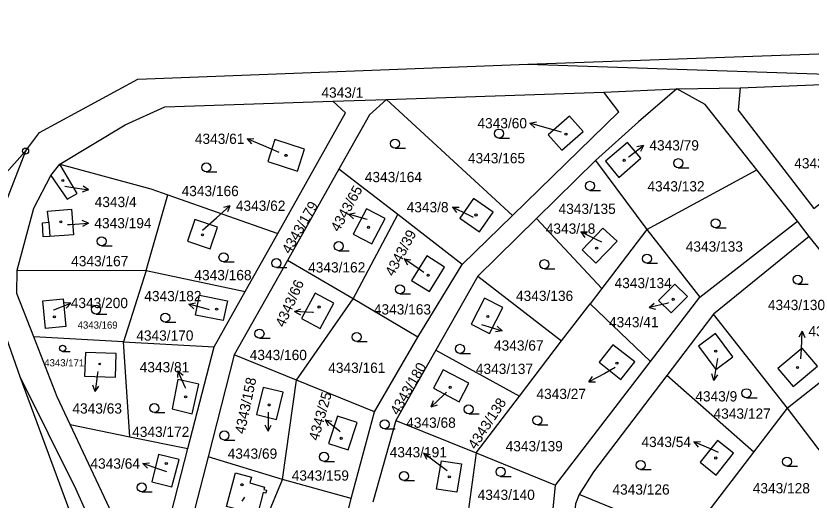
# Model space of a CAD drawing. Extents: x -733394 to -722299, y -1082822 to -1075049.
# Drawn here: x -729669.4 to -729537.5, y -1077903.2 to -1077822.8 of the extents above; entities that cross this region are included whole.
import ezdxf

# ---------------------------------------------------------------- set-up
doc = ezdxf.new("R2010")
doc.units = 0
for name, color, linetype in [('Hranice parcel', 7, 'Continuous'), ('Parcelní čísla', 7, 'Continuous'), ('Pop  PČ popisy', 7, 'Continuous'), ('Vnitřní kresba', 7, 'Continuous'), ('Značky bodu BP', 7, 'Continuous'), ('Značky budov', 7, 'Continuous'), ('Značky kultur', 7, 'Continuous')]:
    doc.layers.add(name, color=color, linetype=linetype)

msp = doc.modelspace()

# ---------------------------------------------------------------- linework, layer by layer
at = {"layer": 'Hranice parcel'}
for p, q in [((-729549.31, -1077834.75), (-729513.26, -1077833.28)), ((-729607.94, -1077836.69), (-729571.93, -1077835.5)), ((-729571.93, -1077835.5), (-729559.79, -1077834.92)), ((-729559.79, -1077834.92), (-729549.31, -1077834.75)), ((-729616.86, -1077836.99), (-729607.94, -1077836.69)), ((-729587.08, -1077855.95), (-729607.94, -1077836.69)), ((-729677.33, -1077855.84), (-729667.81, -1077845.25)), ((-729667.81, -1077845.25), (-729675.27, -1077864.38)), ((-729573.27, -1077846.82), (-729583.07, -1077856.44)), ((-729573.27, -1077846.82), (-729564.79, -1077858.28)), ((-729663.65, -1077849.32), (-729662.16, -1077847.4)), ((-729615.86, -1077848.27), (-729624.38, -1077863.39)), ((-729606.1, -1077855.8), (-729615.86, -1077848.27)), ((-729564.79, -1077858.28), (-729546.55, -1077848.34)), ((-729539.8, -1077856.9), (-729546.55, -1077848.34)), ((-729647.8, -1077865.06), (-729644.24, -1077852.49)), ((-729644.24, -1077852.49), (-729626, -1077858.95)), ((-729613.48, -1077869.77), (-729606.1, -1077855.8)), ((-729595.38, -1077864.05), (-729606.1, -1077855.8)), ((-729595.38, -1077864.05), (-729587.08, -1077855.95)), ((-729583.07, -1077856.44), (-729592.83, -1077866.02)), ((-729583.07, -1077856.44), (-729572.23, -1077868.03)), ((-729555.96, -1077869.5), (-729539.8, -1077856.9)), ((-729537.82, -1077859.41), (-729539.8, -1077856.9)), ((-729631.39, -1077868.53), (-729626, -1077858.95)), ((-729564.79, -1077858.28), (-729572.23, -1077868.03)), ((-729564.79, -1077858.28), (-729555.96, -1077869.5)), ((-729537.82, -1077859.41), (-729553.73, -1077872.32)), ((-729525.41, -1077875.14), (-729537.82, -1077859.41)), ((-729675.27, -1077864.38), (-729668.75, -1077882.65)), ((-729624.38, -1077863.39), (-729633.23, -1077879.08)), ((-729613.48, -1077869.77), (-729624.38, -1077863.39)), ((-729602.78, -1077876.16), (-729595.38, -1077864.05)), ((-729669.21, -1077865.04), (-729647.8, -1077865.06)), ((-729647.8, -1077865.06), (-729651.59, -1077876.89)), ((-729647.8, -1077865.06), (-729631.39, -1077868.53)), ((-729592.83, -1077866.02), (-729599.78, -1077878.28)), ((-729592.83, -1077866.02), (-729578.9, -1077876.76)), ((-729572.23, -1077868.03), (-729574.19, -1077870.6)), ((-729636.56, -1077877.73), (-729631.39, -1077868.53)), ((-729622.86, -1077883.28), (-729613.48, -1077869.77)), ((-729602.78, -1077876.16), (-729613.48, -1077869.77)), ((-729564.14, -1077880.15), (-729555.96, -1077869.5)), ((-729578.9, -1077876.76), (-729574.19, -1077870.6)), ((-729574.19, -1077870.6), (-729564.14, -1077880.15)), ((-729553.73, -1077872.32), (-729561.44, -1077882.47)), ((-729541.43, -1077887.94), (-729553.73, -1077872.32)), ((-729651.59, -1077876.89), (-729666.45, -1077876.06)), ((-729609.95, -1077888.51), (-729602.78, -1077876.16)), ((-729525.41, -1077875.14), (-729541.43, -1077887.94)), ((-729650.53, -1077892.65), (-729651.59, -1077876.89)), ((-729651.59, -1077876.89), (-729636.56, -1077877.73)), ((-729585.89, -1077885.92), (-729578.9, -1077876.76)), ((-729640.9, -1077894.62), (-729636.56, -1077877.73)), ((-729599.78, -1077878.28), (-729606.38, -1077889.95)), ((-729599.78, -1077878.28), (-729585.89, -1077885.92)), ((-729633.23, -1077879.08), (-729637.55, -1077896.01)), ((-729622.86, -1077883.28), (-729633.23, -1077879.08)), ((-729579.9, -1077900.68), (-729564.14, -1077880.15)), ((-729547.02, -1077895.24), (-729561.44, -1077882.47)), ((-729625.23, -1077899.74), (-729622.86, -1077883.28)), ((-729609.95, -1077888.51), (-729622.86, -1077883.28)), ((-729593.08, -1077895.34), (-729585.89, -1077885.92)), ((-729547.02, -1077895.24), (-729541.43, -1077887.94)), ((-729529.41, -1077903.77), (-729541.43, -1077887.94)), ((-729613.82, -1077902.92), (-729609.95, -1077888.51)), ((-729648.42, -1077916.16), (-729660.41, -1077890.63)), ((-729660.41, -1077890.63), (-729650.53, -1077892.65)), ((-729606.38, -1077889.95), (-729610.2, -1077903.5)), ((-729606.38, -1077889.95), (-729593.08, -1077895.34)), ((-729650.53, -1077892.65), (-729640.9, -1077894.62)), ((-729637.55, -1077896.01), (-729641.89, -1077913.03)), ((-729625.23, -1077899.74), (-729637.55, -1077896.01)), ((-729593.08, -1077895.34), (-729594.79, -1077907.72)), ((-729593.08, -1077895.34), (-729579.9, -1077900.68)), ((-729557.98, -1077909.55), (-729547.02, -1077895.24)), ((-729631.27, -1077914.26), (-729625.23, -1077899.74)), ((-729613.82, -1077902.92), (-729625.23, -1077899.74)), ((-729581.26, -1077914.24), (-729579.9, -1077900.68)), ((-729557.98, -1077909.55), (-729575.99, -1077902.26)), ((-729617.11, -1077915.9), (-729613.82, -1077902.92))]:
    msp.add_line(p, q, dxfattribs=at)
for points in [[(-729584.53, -1077830.82), (-729511.39, -1077828.22), (-729503.43, -1077827.46), (-729475.38, -1077824.79), (-729463.28, -1077823.55), (-729456.4, -1077822.82)], [(-729584.53, -1077830.82), (-729528.32, -1077832.73), (-729478.29, -1077828.76), (-729456.16, -1077825.12)], [(-729667.81, -1077845.25), (-729665.54, -1077842.16), (-729649.22, -1077833.32), (-729584.53, -1077830.82)], [(-729549.31, -1077834.75), (-729549.62, -1077838.49), (-729537.08, -1077854.76), (-729513.33, -1077836.06), (-729513.26, -1077833.28)], [(-729587.08, -1077855.95), (-729569.44, -1077838.75), (-729571.93, -1077835.5)], [(-729559.79, -1077834.92), (-729566.15, -1077840.39), (-729573.27, -1077846.82)], [(-729546.55, -1077848.34), (-729555.08, -1077837.54), (-729559.79, -1077834.92)], [(-729607.94, -1077836.69), (-729610.77, -1077839.24), (-729615.86, -1077848.27)], [(-729662.16, -1077847.4), (-729651.29, -1077840.91), (-729644.75, -1077837.91), (-729616.86, -1077836.99)], [(-729626, -1077858.95), (-729614.73, -1077838.91), (-729616.86, -1077836.99)], [(-729578.87, -1077845.12), (-729575.34, -1077842), (-729577.6, -1077839.45), (-729581.12, -1077842.57), (-729578.87, -1077845.12)], [(-729621.55, -1077844.94), (-729626.45, -1077843.33), (-729627.64, -1077846.96), (-729622.73, -1077848.57), (-729621.55, -1077844.94)], [(-729567.95, -1077843.85), (-729571.65, -1077846.93), (-729569.4, -1077849.61), (-729565.76, -1077846.45), (-729567.95, -1077843.85)], [(-729663.65, -1077849.32), (-729660.93, -1077853.23), (-729659.24, -1077852.31), (-729662.16, -1077847.4)], [(-729662.16, -1077847.4), (-729647.02, -1077851.51), (-729644.24, -1077852.49)], [(-729669.21, -1077865.04), (-729666.43, -1077854.72), (-729663.65, -1077849.32)], [(-729592.55, -1077858.65), (-729590.26, -1077855.41), (-729593.51, -1077853.11), (-729595.8, -1077856.36), (-729592.55, -1077858.65)], [(-729665.04, -1077857.14), (-729663.95, -1077857.06), (-729664.17, -1077855.23), (-729660.19, -1077854.88), (-729659.9, -1077859.13), (-729663.78, -1077859.41), (-729664.88, -1077859.48), (-729665.04, -1077857.14)], [(-729610.37, -1077860.67), (-729608.18, -1077856.45), (-729611.29, -1077854.83), (-729613.48, -1077859.05), (-729610.37, -1077860.67)], [(-729636, -1077857.9), (-729639.75, -1077856.62), (-729640.97, -1077860.19), (-729637.22, -1077861.47), (-729636, -1077857.9)], [(-729575.5, -1077861.63), (-729573.21, -1077863.84), (-729569.71, -1077860.22), (-729572.09, -1077858.02), (-729575.5, -1077861.63)], [(-729601.27, -1077862.66), (-729603.79, -1077866.72), (-729600.84, -1077868.56), (-729598.31, -1077864.49), (-729601.27, -1077862.66)], [(-729666.45, -1077876.06), (-729669.26, -1077868.86), (-729669.21, -1077865.04)], [(-729558.04, -1077869.39), (-729560.1, -1077867.33), (-729562.82, -1077870.07), (-729560.76, -1077872.12), (-729558.04, -1077869.39)], [(-729661.59, -1077869.79), (-729661.15, -1077874.36), (-729664.52, -1077874.68), (-729664.97, -1077870.12), (-729661.59, -1077869.79)], [(-729638.98, -1077869.14), (-729634.33, -1077870.09), (-729635.04, -1077873.36), (-729639.65, -1077872.49), (-729638.98, -1077869.14)], [(-729616.7, -1077870.51), (-729619.81, -1077868.83), (-729622.07, -1077873.01), (-729618.95, -1077874.69), (-729616.7, -1077870.51)], [(-729588.66, -1077871.2), (-729591.69, -1077869.64), (-729593.91, -1077873.97), (-729590.88, -1077875.53), (-729588.66, -1077871.2)], [(-729660.41, -1077890.63), (-729662.57, -1077886.03), (-729666.45, -1077876.06)], [(-729550.51, -1077879.41), (-729553.38, -1077875.54), (-729556.18, -1077877.61), (-729553.32, -1077881.49), (-729550.51, -1077879.41)], [(-729566.75, -1077880.2), (-729570.39, -1077877.4), (-729572.69, -1077880.29), (-729569.07, -1077883.14), (-729566.75, -1077880.2)], [(-729652.93, -1077882.76), (-729652.79, -1077878.86), (-729657.9, -1077878.67), (-729658.04, -1077882.58), (-729652.93, -1077882.76)], [(-729540.5, -1077884.34), (-729536.47, -1077880.95), (-729538.99, -1077877.96), (-729543.02, -1077881.35), (-729540.5, -1077884.34)], [(-729600.16, -1077884.61), (-729595.88, -1077886.85), (-729594.27, -1077883.77), (-729598.54, -1077881.58), (-729600.16, -1077884.61)], [(-729668.75, -1077882.65), (-729659.48, -1077901.34), (-729652.78, -1077916.35), (-729643.8, -1077935.33), (-729632.76, -1077952.54), (-729622.2, -1077964.95), (-729556.97, -1078018.84)], [(-729668.75, -1077882.65), (-729648.84, -1077936.68), (-729633.06, -1077960.71), (-729557.22, -1078018.79)], [(-729561.44, -1077882.47), (-729573.6, -1077898.46), (-729575.99, -1077902.26)], [(-729642.57, -1077883.15), (-729643.53, -1077888.05), (-729640.21, -1077888.88), (-729639.1, -1077883.93), (-729642.57, -1077883.15)], [(-729628.43, -1077884.46), (-729629.53, -1077888.99), (-729626.2, -1077889.79), (-729625.11, -1077885.26), (-729628.43, -1077884.46)], [(-729614.3, -1077894.81), (-729612.84, -1077890.31), (-729616.09, -1077889.26), (-729617.55, -1077893.76), (-729614.3, -1077894.81)], [(-729553.04, -1077893.26), (-729555.93, -1077896.89), (-729553.27, -1077899.02), (-729550.37, -1077895.39), (-729553.04, -1077893.26)], [(-729648.42, -1077916.16), (-729646.44, -1077916.19), (-729640.9, -1077894.62)], [(-729642.35, -1077896.42), (-729645.76, -1077895.58), (-729646.89, -1077900.16), (-729643.58, -1077900.98), (-729642.35, -1077896.42)], [(-729598.85, -1077896.64), (-729595.51, -1077897.18), (-729596.28, -1077901.88), (-729599.64, -1077901.33), (-729598.85, -1077896.64)], [(-729629.37, -1077905.57), (-729634.48, -1077904.23), (-729633.02, -1077898.63), (-729630.32, -1077899.34), (-729630.6, -1077900.33), (-729628.19, -1077901), (-729628.3, -1077901.41), (-729627.86, -1077901.52), (-729627.98, -1077902.01), (-729628.42, -1077901.9), (-729629.37, -1077905.57)], [(-729575.99, -1077902.26), (-729576.6, -1077903.78), (-729577.71, -1077915.07)]]:
    msp.add_lwpolyline(points, dxfattribs=at)
at = {"layer": 'Pop  PČ popisy'}
for p, q in [((-729584.19, -1077840.61), (-729583.08, -1077840.41)), ((-729581.3, -1077841.44), (-729584.19, -1077840.61)), ((-729584.19, -1077840.61), (-729583.36, -1077841.37)), ((-729578.95, -1077842.09), (-729581.3, -1077841.44)), ((-729631.06, -1077843.22), (-729629.95, -1077843.15)), ((-729628.3, -1077844.39), (-729631.06, -1077843.22)), ((-729631.06, -1077843.22), (-729630.34, -1077844.07)), ((-729625.77, -1077845.48), (-729628.3, -1077844.39)), ((-729567.7, -1077846.16), (-729565.34, -1077844.31)), ((-729565.34, -1077844.31), (-729566.43, -1077844.53)), ((-729565.34, -1077844.31), (-729565.82, -1077845.32)), ((-729567.82, -1077846.26), (-729567.7, -1077846.16)), ((-729661.31, -1077851.08), (-729660.32, -1077851.24)), ((-729660.32, -1077851.24), (-729657.36, -1077851.71)), ((-729657.36, -1077851.71), (-729658.27, -1077851.06)), ((-729657.36, -1077851.71), (-729658.42, -1077852.05)), ((-729636.16, -1077856.33), (-729633.93, -1077854.32)), ((-729633.93, -1077854.32), (-729635.01, -1077854.62)), ((-729633.93, -1077854.32), (-729634.34, -1077855.36)), ((-729597.01, -1077854.58), (-729595.89, -1077854.57)), ((-729594.31, -1077855.9), (-729597.01, -1077854.58)), ((-729597.01, -1077854.58), (-729596.33, -1077855.47)), ((-729638.45, -1077858.4), (-729636.16, -1077856.33)), ((-729614.24, -1077855.72), (-729613.14, -1077855.52)), ((-729611.36, -1077856.55), (-729614.24, -1077855.72)), ((-729614.24, -1077855.72), (-729613.42, -1077856.48)), ((-729611.16, -1077856.61), (-729611.36, -1077856.55)), ((-729593.51, -1077856.29), (-729594.31, -1077855.9)), ((-729660.86, -1077857.44), (-729660.4, -1077857.41)), ((-729660.4, -1077857.41), (-729657.41, -1077857.2)), ((-729657.41, -1077857.2), (-729658.44, -1077856.77)), ((-729657.41, -1077857.2), (-729658.37, -1077857.77)), ((-729575.74, -1077858.68), (-729574.62, -1077858.67)), ((-729573.04, -1077860), (-729575.74, -1077858.68)), ((-729575.74, -1077858.68), (-729575.06, -1077859.57)), ((-729572.25, -1077860.39), (-729573.04, -1077860)), ((-729602.55, -1077864.85), (-729605.01, -1077863.13)), ((-729605.01, -1077863.13), (-729603.9, -1077863.29)), ((-729605.01, -1077863.13), (-729604.48, -1077864.11)), ((-729601.74, -1077865.41), (-729602.55, -1077864.85)), ((-729663.11, -1077871.62), (-729660.33, -1077870.5)), ((-729660.33, -1077870.5), (-729661.44, -1077870.41)), ((-729660.33, -1077870.5), (-729661.07, -1077871.33)), ((-729640.75, -1077870.66), (-729639.65, -1077870.44)), ((-729637.85, -1077871.44), (-729640.75, -1077870.66)), ((-729640.75, -1077870.66), (-729639.91, -1077871.41)), ((-729564.39, -1077871.21), (-729563.53, -1077870.49)), ((-729561.47, -1077870.53), (-729564.39, -1077871.21)), ((-729561.17, -1077870.46), (-729561.47, -1077870.53)), ((-729663.18, -1077871.65), (-729663.11, -1077871.62)), ((-729637.3, -1077871.58), (-729637.85, -1077871.44)), ((-729623.22, -1077871.87), (-729622.19, -1077871.43)), ((-729620.22, -1077872.03), (-729623.22, -1077871.87)), ((-729623.22, -1077871.87), (-729622.24, -1077872.43)), ((-729620.04, -1077872.04), (-729620.22, -1077872.03)), ((-729564.39, -1077871.21), (-729563.31, -1077871.47)), ((-729592.19, -1077874.03), (-729591.65, -1077874.19)), ((-729591.65, -1077874.19), (-729588.78, -1077875.07)), ((-729588.78, -1077875.07), (-729589.88, -1077875.25)), ((-729588.78, -1077875.07), (-729589.59, -1077874.3)), ((-729538.98, -1077875.14), (-729539.54, -1077876.12)), ((-729539.14, -1077878.14), (-729538.98, -1077875.14)), ((-729538.98, -1077875.14), (-729538.54, -1077876.17)), ((-729539.24, -1077879.75), (-729539.14, -1077878.14)), ((-729553.16, -1077880.34), (-729553.63, -1077883.3)), ((-729553.05, -1077879.66), (-729553.16, -1077880.34)), ((-729570, -1077881.19), (-729571.76, -1077882.14)), ((-729655.88, -1077882.19), (-729656.3, -1077885.16)), ((-729655.83, -1077881.85), (-729655.88, -1077882.19)), ((-729642.56, -1077881.71), (-729642.61, -1077882.83)), ((-729641.34, -1077884.45), (-729642.56, -1077881.71)), ((-729642.56, -1077881.71), (-729641.7, -1077882.42)), ((-729571.76, -1077882.14), (-729574.41, -1077883.55)), ((-729574.41, -1077883.55), (-729573.76, -1077882.64)), ((-729553.63, -1077883.3), (-729553.97, -1077882.24)), ((-729553.63, -1077883.3), (-729552.98, -1077882.39)), ((-729656.3, -1077885.16), (-729656.65, -1077884.1)), ((-729656.3, -1077885.16), (-729655.66, -1077884.24)), ((-729574.41, -1077883.55), (-729573.29, -1077883.52)), ((-729641.25, -1077884.66), (-729641.34, -1077884.45)), ((-729598.37, -1077885.63), (-729600.57, -1077887.68)), ((-729597.99, -1077885.28), (-729598.37, -1077885.63)), ((-729600.57, -1077887.68), (-729600.17, -1077886.63)), ((-729600.57, -1077887.68), (-729599.49, -1077887.36)), ((-729627.58, -1077888.57), (-729627.58, -1077888.75)), ((-729627.58, -1077888.75), (-729627.58, -1077891.75)), ((-729627.58, -1077891.75), (-729628.08, -1077890.75)), ((-729627.58, -1077891.75), (-729627.08, -1077890.75)), ((-729615.77, -1077891.74), (-729618.1, -1077889.85)), ((-729618.1, -1077889.85), (-729617.01, -1077890.09)), ((-729618.1, -1077889.85), (-729617.64, -1077890.87)), ((-729615.65, -1077891.84), (-729615.77, -1077891.74)), ((-729556.97, -1077893.51), (-729555.85, -1077893.44)), ((-729554.21, -1077894.68), (-729556.97, -1077893.51)), ((-729556.97, -1077893.51), (-729556.25, -1077894.36)), ((-729552.86, -1077895.25), (-729554.21, -1077894.68)), ((-729599.41, -1077897.2), (-729601.81, -1077895.39)), ((-729601.81, -1077895.39), (-729600.71, -1077895.6)), ((-729601.81, -1077895.39), (-729601.31, -1077896.4)), ((-729648.38, -1077897.1), (-729647.27, -1077896.96)), ((-729645.54, -1077898.08), (-729648.38, -1077897.1)), ((-729648.38, -1077897.1), (-729647.59, -1077897.9)), ((-729597.87, -1077898.34), (-729599.41, -1077897.2)), ((-729644.38, -1077898.47), (-729645.54, -1077898.08)), ((-729631.52, -1077902.7), (-729631.97, -1077903.33))]:
    msp.add_line(p, q, dxfattribs=at)
at = {"layer": 'Vnitřní kresba'}
msp.add_line((-729663.95, -1077857.06), (-729663.78, -1077859.41), dxfattribs=at)
at = {"layer": 'Značky bodu BP'}
for radius in [0.5, 0.0303]:
    msp.add_circle((-729667.81, -1077845.25), radius, dxfattribs=at)
at = {"layer": 'Značky budov'}
for centre, radius in [((-729578.19, -1077842.46), 0.175), ((-729624.62, -1077845.97), 0.175), ((-729568.52, -1077846.78), 0.175), ((-729661.64, -1077850.13), 0.175), ((-729593.1, -1077855.86), 0.175), ((-729661.96, -1077857), 0.175), ((-729610.94, -1077857.91), 0.175), ((-729638.47, -1077859.16), 0.175), ((-729573.1, -1077861.35), 0.175), ((-729601.03, -1077865.86), 0.175), ((-729560.41, -1077869.85), 0.175), ((-729619.14, -1077871.13), 0.175), ((-729636.13, -1077871.49), 0.175), ((-729663.04, -1077872.75), 0.175), ((-729591.14, -1077872.69), 0.175), ((-729553.34, -1077878.46), 0.175), ((-729569.73, -1077880.46), 0.175), ((-729655.51, -1077880.58), 0.122), ((-729539.78, -1077881.17), 0.175), ((-729597.38, -1077884.46), 0.175), ((-729641.27, -1077886.03), 0.175), ((-729627.41, -1077887.38), 0.175), ((-729615.47, -1077892.93), 0.175), ((-729553.34, -1077896.19), 0.175), ((-729644.48, -1077897.11), 0.175), ((-729597.54, -1077899.31), 0.175), ((-729631.93, -1077900.62), 0.175)]:
    msp.add_circle(centre, radius, dxfattribs=at)
at = {"layer": 'Značky kultur'}
for p, q in [((-729589.3, -1077843.09), (-729587.55, -1077843.09)), ((-729606.53, -1077844.76), (-729604.78, -1077844.76)), ((-729559.56, -1077848.01), (-729557.81, -1077848.01)), ((-729637.84, -1077848.72), (-729636.09, -1077848.72)), ((-729574.22, -1077851.77), (-729572.47, -1077851.77)), ((-729553.37, -1077857.98), (-729551.62, -1077857.98)), ((-729655.22, -1077860.97), (-729653.47, -1077860.97)), ((-729615.87, -1077861.78), (-729614.12, -1077861.78)), ((-729634.99, -1077863.63), (-729633.24, -1077863.63)), ((-729564.75, -1077863.87), (-729563, -1077863.87)), ((-729626.21, -1077864.6), (-729624.46, -1077864.6)), ((-729581.77, -1077864.77), (-729580.02, -1077864.77)), ((-729539.75, -1077867.32), (-729538, -1077867.32)), ((-729605.73, -1077868.95), (-729603.98, -1077868.95)), ((-729656.12, -1077872.3), (-729654.37, -1077872.3)), ((-729644.66, -1077873.66), (-729642.91, -1077873.66)), ((-729629.02, -1077876.31), (-729627.27, -1077876.31)), ((-729612.89, -1077876.87), (-729611.14, -1077876.87)), ((-729661.68, -1077878.53), (-729660.45, -1077878.53)), ((-729595.78, -1077878.82), (-729594.03, -1077878.82)), ((-729548.24, -1077886.18), (-729546.49, -1077886.18)), ((-729646.46, -1077888.66), (-729644.71, -1077888.66)), ((-729594.32, -1077888.87), (-729592.57, -1077888.87)), ((-729582.92, -1077890.68), (-729581.17, -1077890.68)), ((-729608.25, -1077891.35), (-729606.5, -1077891.35)), ((-729634.84, -1077893.2), (-729633.09, -1077893.2)), ((-729618.31, -1077896.74), (-729616.56, -1077896.74)), ((-729565.8, -1077898.11), (-729564.05, -1077898.11)), ((-729541.53, -1077897.55), (-729539.78, -1077897.55)), ((-729605.06, -1077899.94), (-729603.31, -1077899.94)), ((-729589.04, -1077899.23), (-729587.29, -1077899.23)), ((-729648.55, -1077901.82), (-729646.8, -1077901.82))]:
    msp.add_line(p, q, dxfattribs=at)
for centre, radius in [((-729589.3, -1077842.34), 0.75), ((-729606.53, -1077844.01), 0.75), ((-729637.84, -1077847.97), 0.75), ((-729559.56, -1077847.26), 0.75), ((-729574.22, -1077851.02), 0.75), ((-729553.37, -1077857.23), 0.75), ((-729655.22, -1077860.22), 0.75), ((-729615.87, -1077861.03), 0.75), ((-729634.99, -1077862.88), 0.75), ((-729626.21, -1077863.85), 0.75), ((-729564.75, -1077863.12), 0.75), ((-729581.77, -1077864.02), 0.75), ((-729539.75, -1077866.57), 0.75), ((-729605.73, -1077868.2), 0.75), ((-729656.12, -1077871.55), 0.75), ((-729644.66, -1077872.91), 0.75), ((-729629.02, -1077875.56), 0.75), ((-729612.89, -1077876.12), 0.75), ((-729661.68, -1077878), 0.525), ((-729595.78, -1077878.07), 0.75), ((-729548.24, -1077885.43), 0.75), ((-729646.46, -1077887.91), 0.75), ((-729594.32, -1077888.12), 0.75), ((-729582.92, -1077889.93), 0.75), ((-729608.25, -1077890.6), 0.75), ((-729634.84, -1077892.45), 0.75), ((-729618.31, -1077895.99), 0.75), ((-729541.53, -1077896.8), 0.75), ((-729565.8, -1077897.36), 0.75), ((-729605.06, -1077899.19), 0.75), ((-729589.04, -1077898.48), 0.75), ((-729648.55, -1077901.07), 0.75)]:
    msp.add_circle(centre, radius, dxfattribs=at)

# ---------------------------------------------------------------- texts
at = {"layer": 'Parcelní čísla'}
for s, height, p in [('4343/1', 1.7, (-729618.75, -1077836.4)), ('4343/60', 1.7, (-729592.87, -1077841.48)), ('4343/61', 1.7, (-729639.74, -1077844.06)), ('4343/79', 1.7, (-729564.35, -1077845.15)), ('4343/165', 1.7, (-729594.45, -1077847.28)), ('4343/131', 1.7, (-729540.32, -1077848.13)), ('4343/164', 1.7, (-729611.55, -1077850.41)), ('4343/166', 1.7, (-729641.94, -1077852.73)), ('4343/132', 1.7, (-729564.67, -1077851.95)), ('4343/4', 1.7, (-729656.36, -1077854.55)), ('4343/62', 1.7, (-729632.94, -1077855.17)), ('4343/8', 1.7, (-729604.61, -1077855.42)), ('4343/135', 1.7, (-729579.41, -1077855.68)), ('4343/194', 1.7, (-729656.41, -1077858.06)), ('4343/18', 1.7, (-729581.53, -1077858.97)), ('4343/133', 1.7, (-729558.31, -1077861.94)), ('4343/167', 1.7, (-729660.26, -1077864.36)), ('4343/162', 1.7, (-729620.95, -1077865.4)), ('4343/168', 1.7, (-729639.82, -1077866.68)), ('4343/134', 1.7, (-729570.12, -1077868)), ('4343/182', 1.7, (-729648.13, -1077870.16)), ('4343/136', 1.7, (-729586.47, -1077870.12)), ('4343/200', 1.7, (-729660.32, -1077871.31)), ('4343/163', 1.7, (-729610.05, -1077872.37)), ('4343/130', 1.7, (-729544.69, -1077871.64)), ('4343/169', 1.19, (-729659.19, -1077874.72)), ('4343/41', 1.7, (-729571.05, -1077874.49)), ('4343/170', 1.7, (-729649.46, -1077876.71)), ('4343/38', 1.7, (-729537.96, -1077876)), ('4343/67', 1.7, (-729590.12, -1077878.36)), ('4343/160', 1.7, (-729630.64, -1077879.94)), ('4343/171', 1.19, (-729664.73, -1077880.98)), ('4343/81', 1.7, (-729648.89, -1077881.97)), ('4343/161', 1.7, (-729617.62, -1077882.06)), ('4343/137', 1.7, (-729593.13, -1077882.24)), ('4343/27', 1.7, (-729583.08, -1077886.39)), ('4343/9', 1.7, (-729556.73, -1077886.8)), ('4343/63', 1.7, (-729660.05, -1077888.81)), ('4343/127', 1.7, (-729553.7, -1077889.67)), ('4343/68', 1.7, (-729604.68, -1077891.17)), ('4343/172', 1.7, (-729650.14, -1077892.69)), ('4343/139', 1.7, (-729588.19, -1077895.07)), ('4343/54', 1.7, (-729565.66, -1077894.37)), ('4343/69', 1.7, (-729634.3, -1077896.31)), ('4343/191', 1.7, (-729607.42, -1077896.08)), ('4343/64', 1.7, (-729657.06, -1077897.96)), ('4343/159', 1.7, (-729623.67, -1077899.94)), ('4343/140', 1.7, (-729592.83, -1077903.14)), ('4343/126', 1.7, (-729570.47, -1077902.26)), ('4343/128', 1.7, (-729547.2, -1077902.05))]:
    msp.add_text(s, height=height, dxfattribs=at).set_placement(p)
for s, rotation, p in [('4343/65', 61, (-729615.85, -1077858.78)), ('4343/179', 60, (-729623.96, -1077862.45)), ('4343/39', 62, (-729606.79, -1077866.17)), ('4343/66', 66, (-729624.93, -1077874.6)), ('4343/180', 60, (-729606, -1077889.2)), ('4343/158', 78, (-729631.49, -1077892.29)), ('4343/25', 74, (-729619.27, -1077893.41)), ('4343/138', 57, (-729593.16, -1077894.88))]:
    msp.add_text(s, height=1.7, rotation=rotation, dxfattribs=at).set_placement(p)

doc.saveas('drawing.dxf')
